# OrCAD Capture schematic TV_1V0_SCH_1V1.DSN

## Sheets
1 Cover: title: 01-Cover; rev: 1.1; company: Shenzhen Test Technology Co., Ltd.; note: TV_V1.0
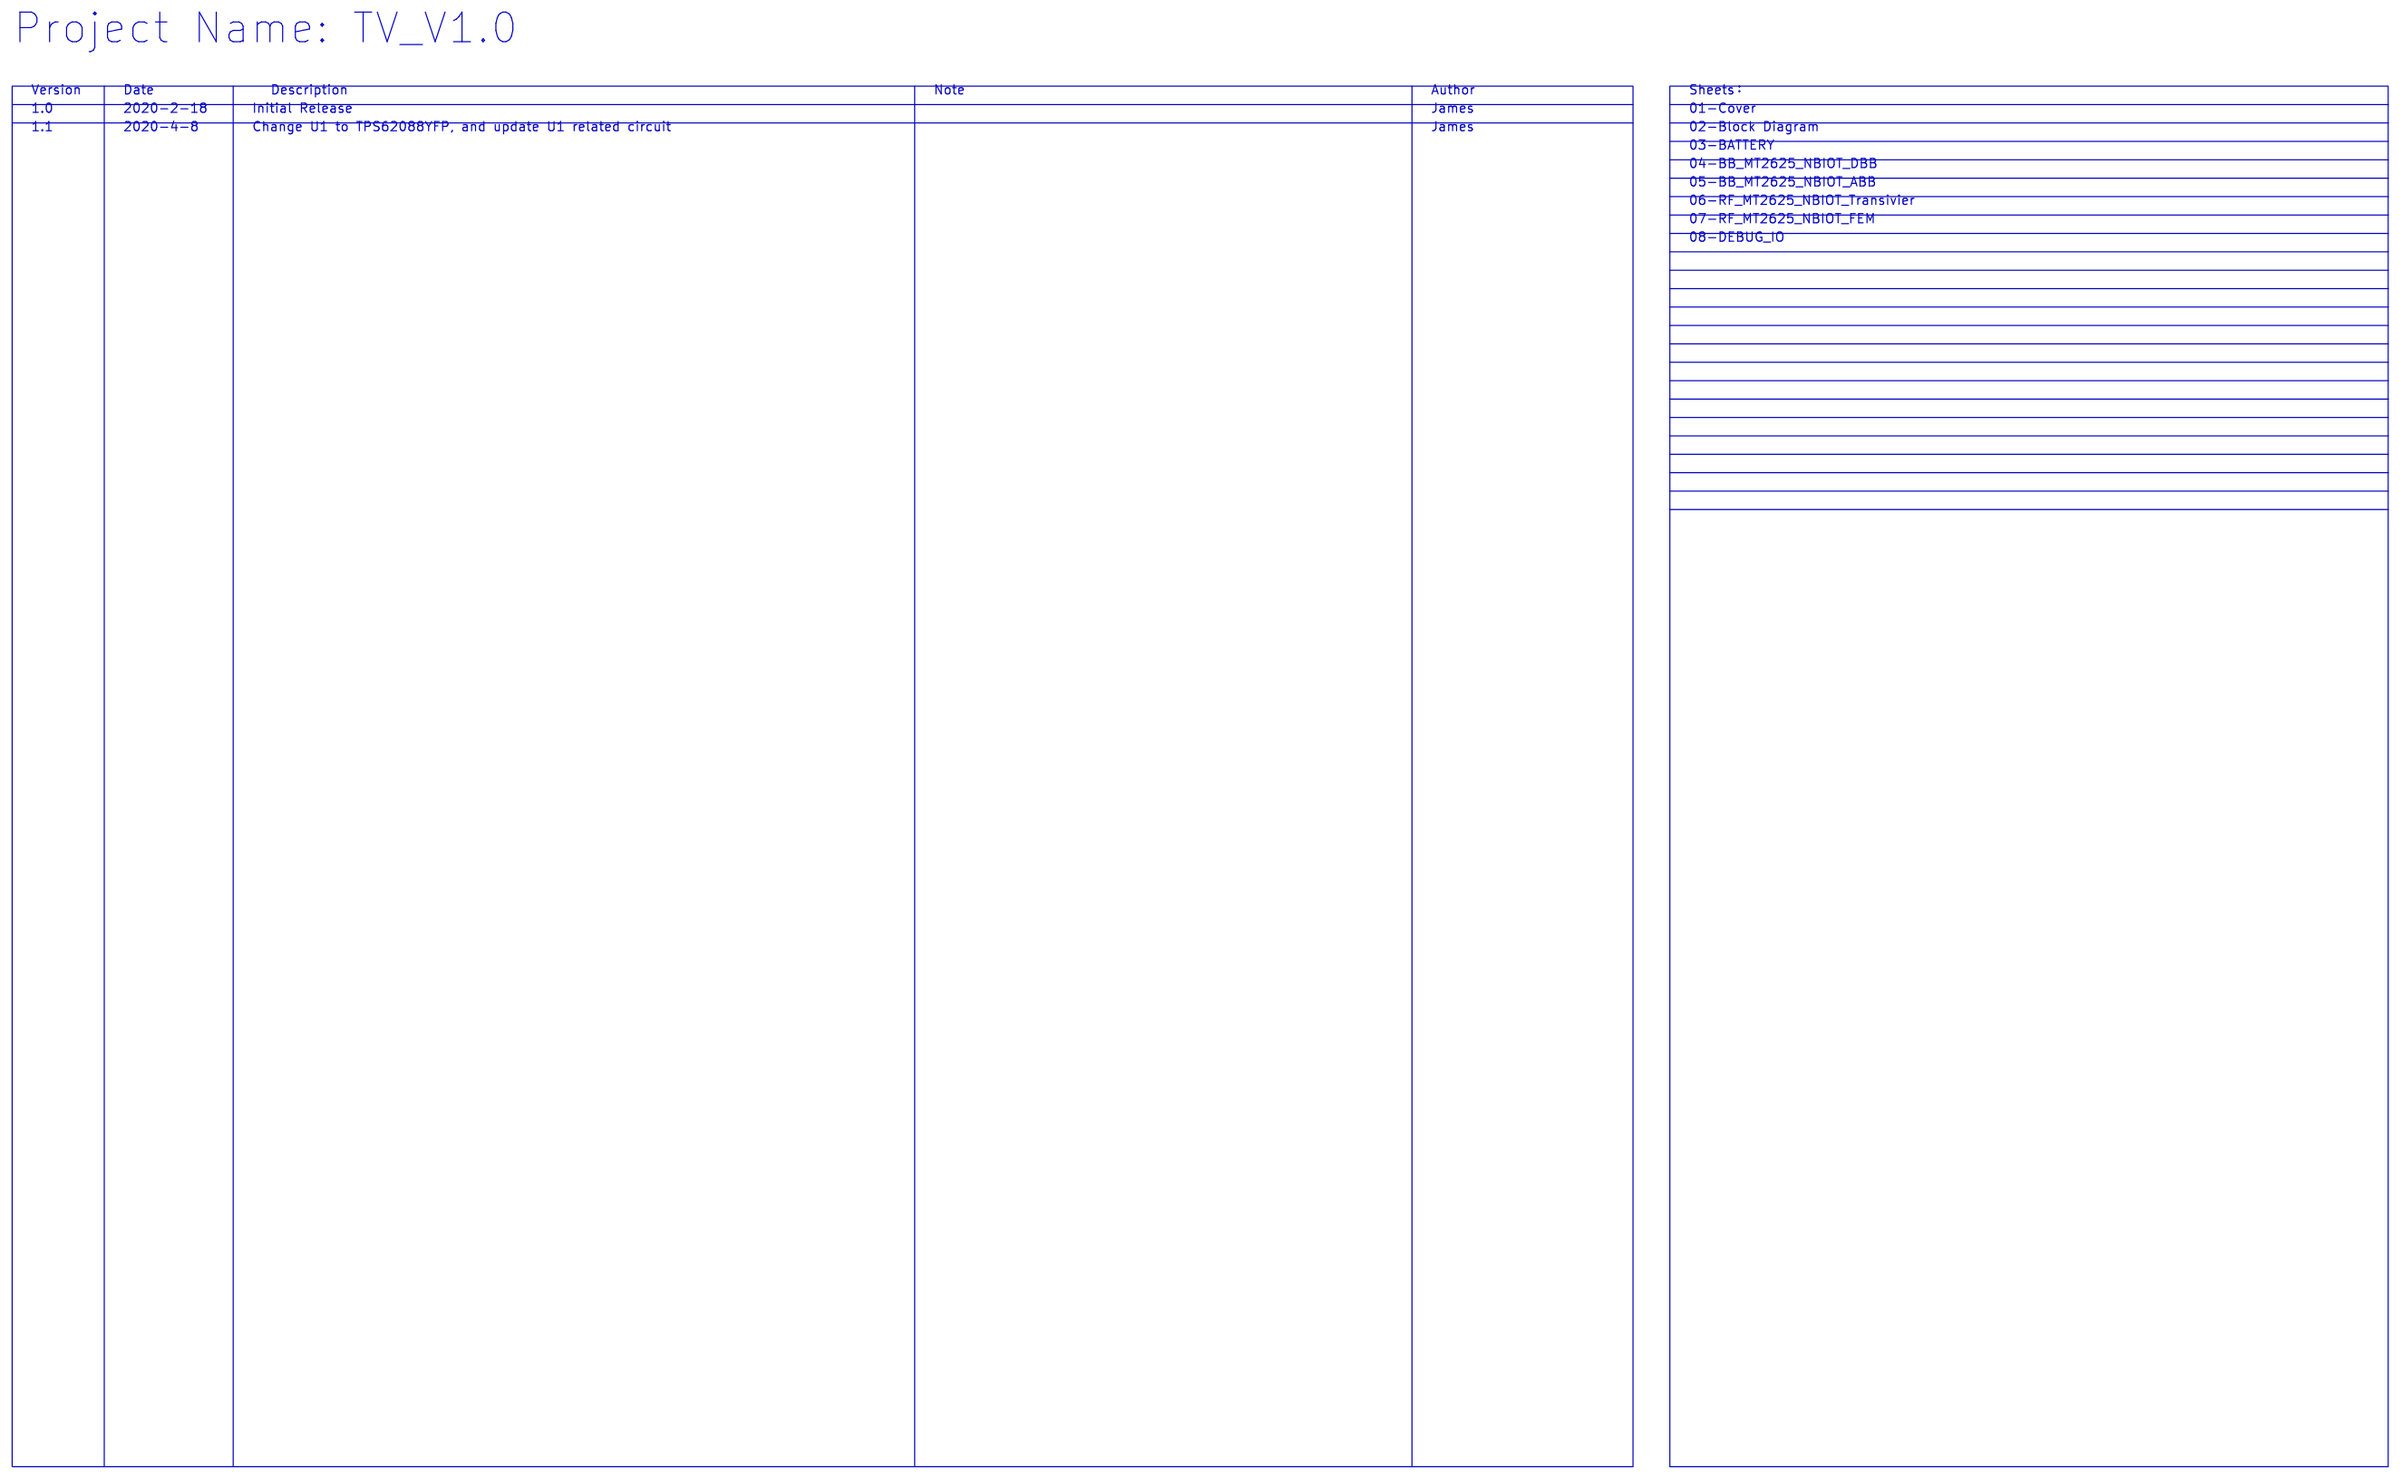
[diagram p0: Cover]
2 Block Diagram: title: 02-Block Diagram
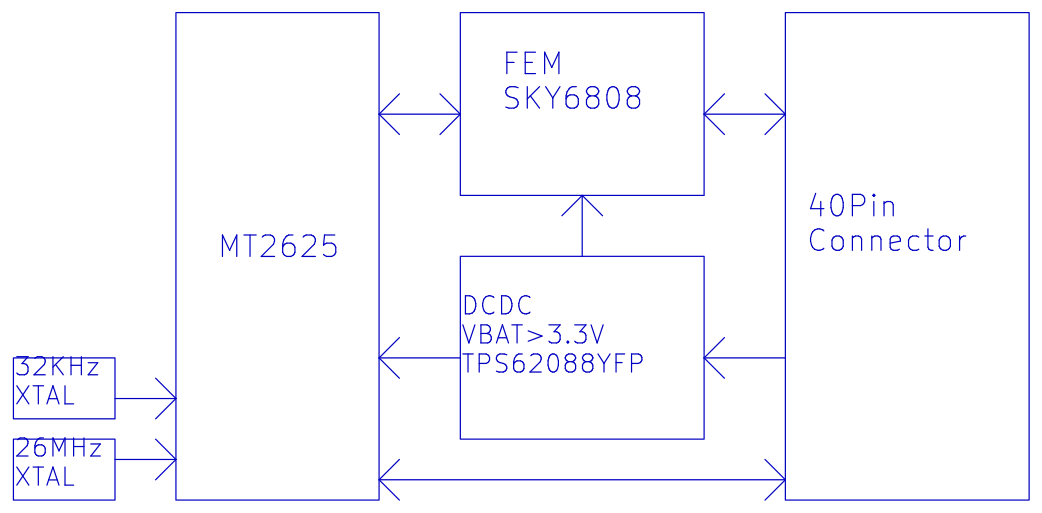
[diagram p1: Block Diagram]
3 BATTERY: size B; title: 03-BATTERY
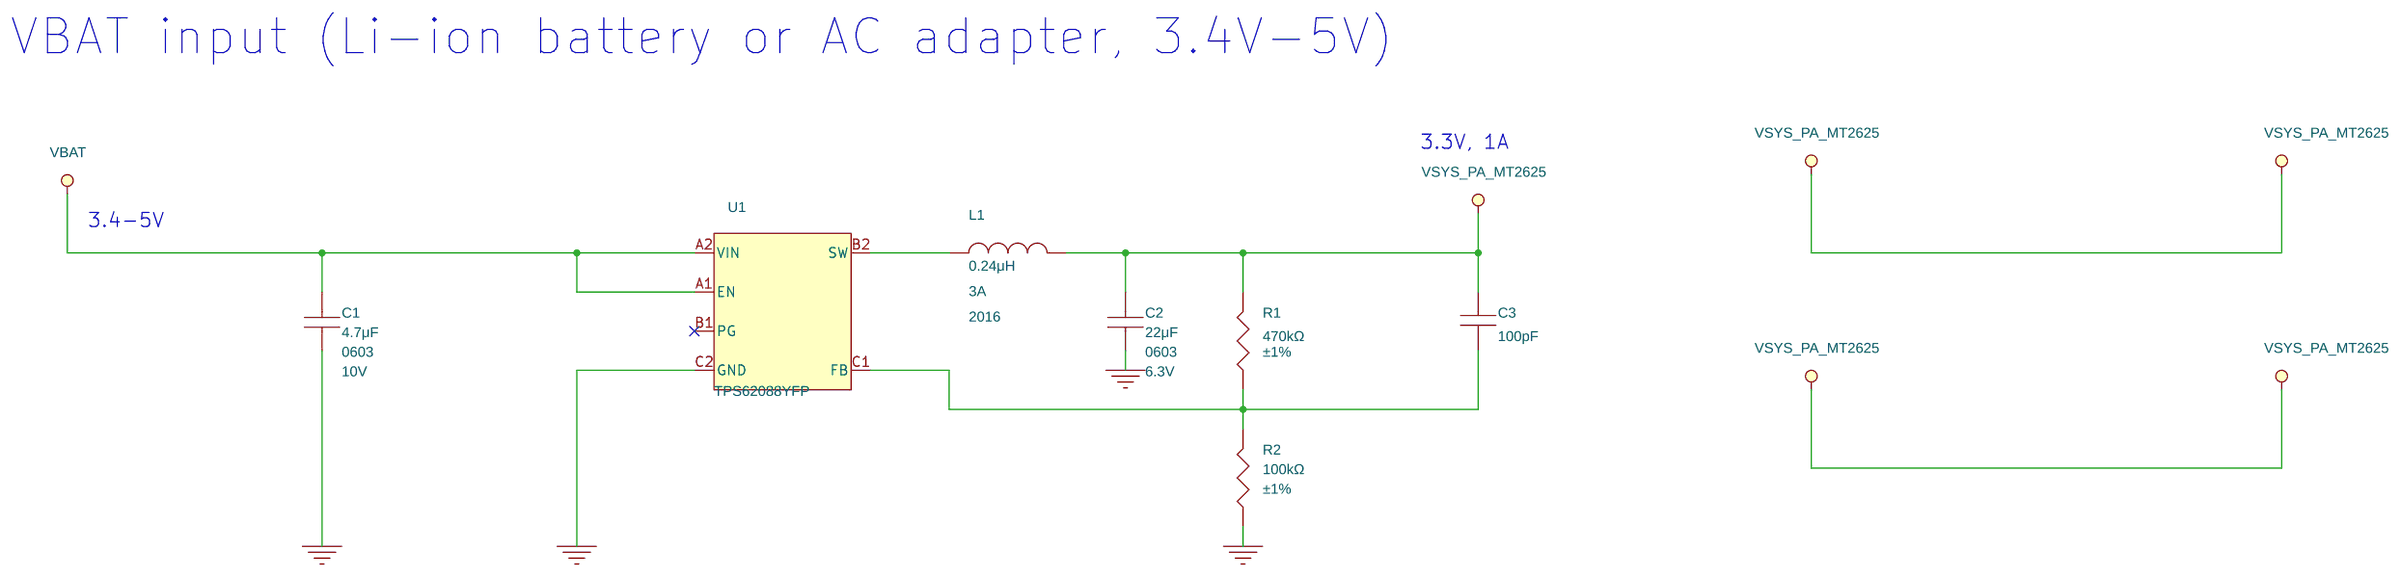
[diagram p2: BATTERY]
4 BB_MT2625_NBIOT_DBB: size B; title: 04-BB_MT2625_NBIOT_DBB
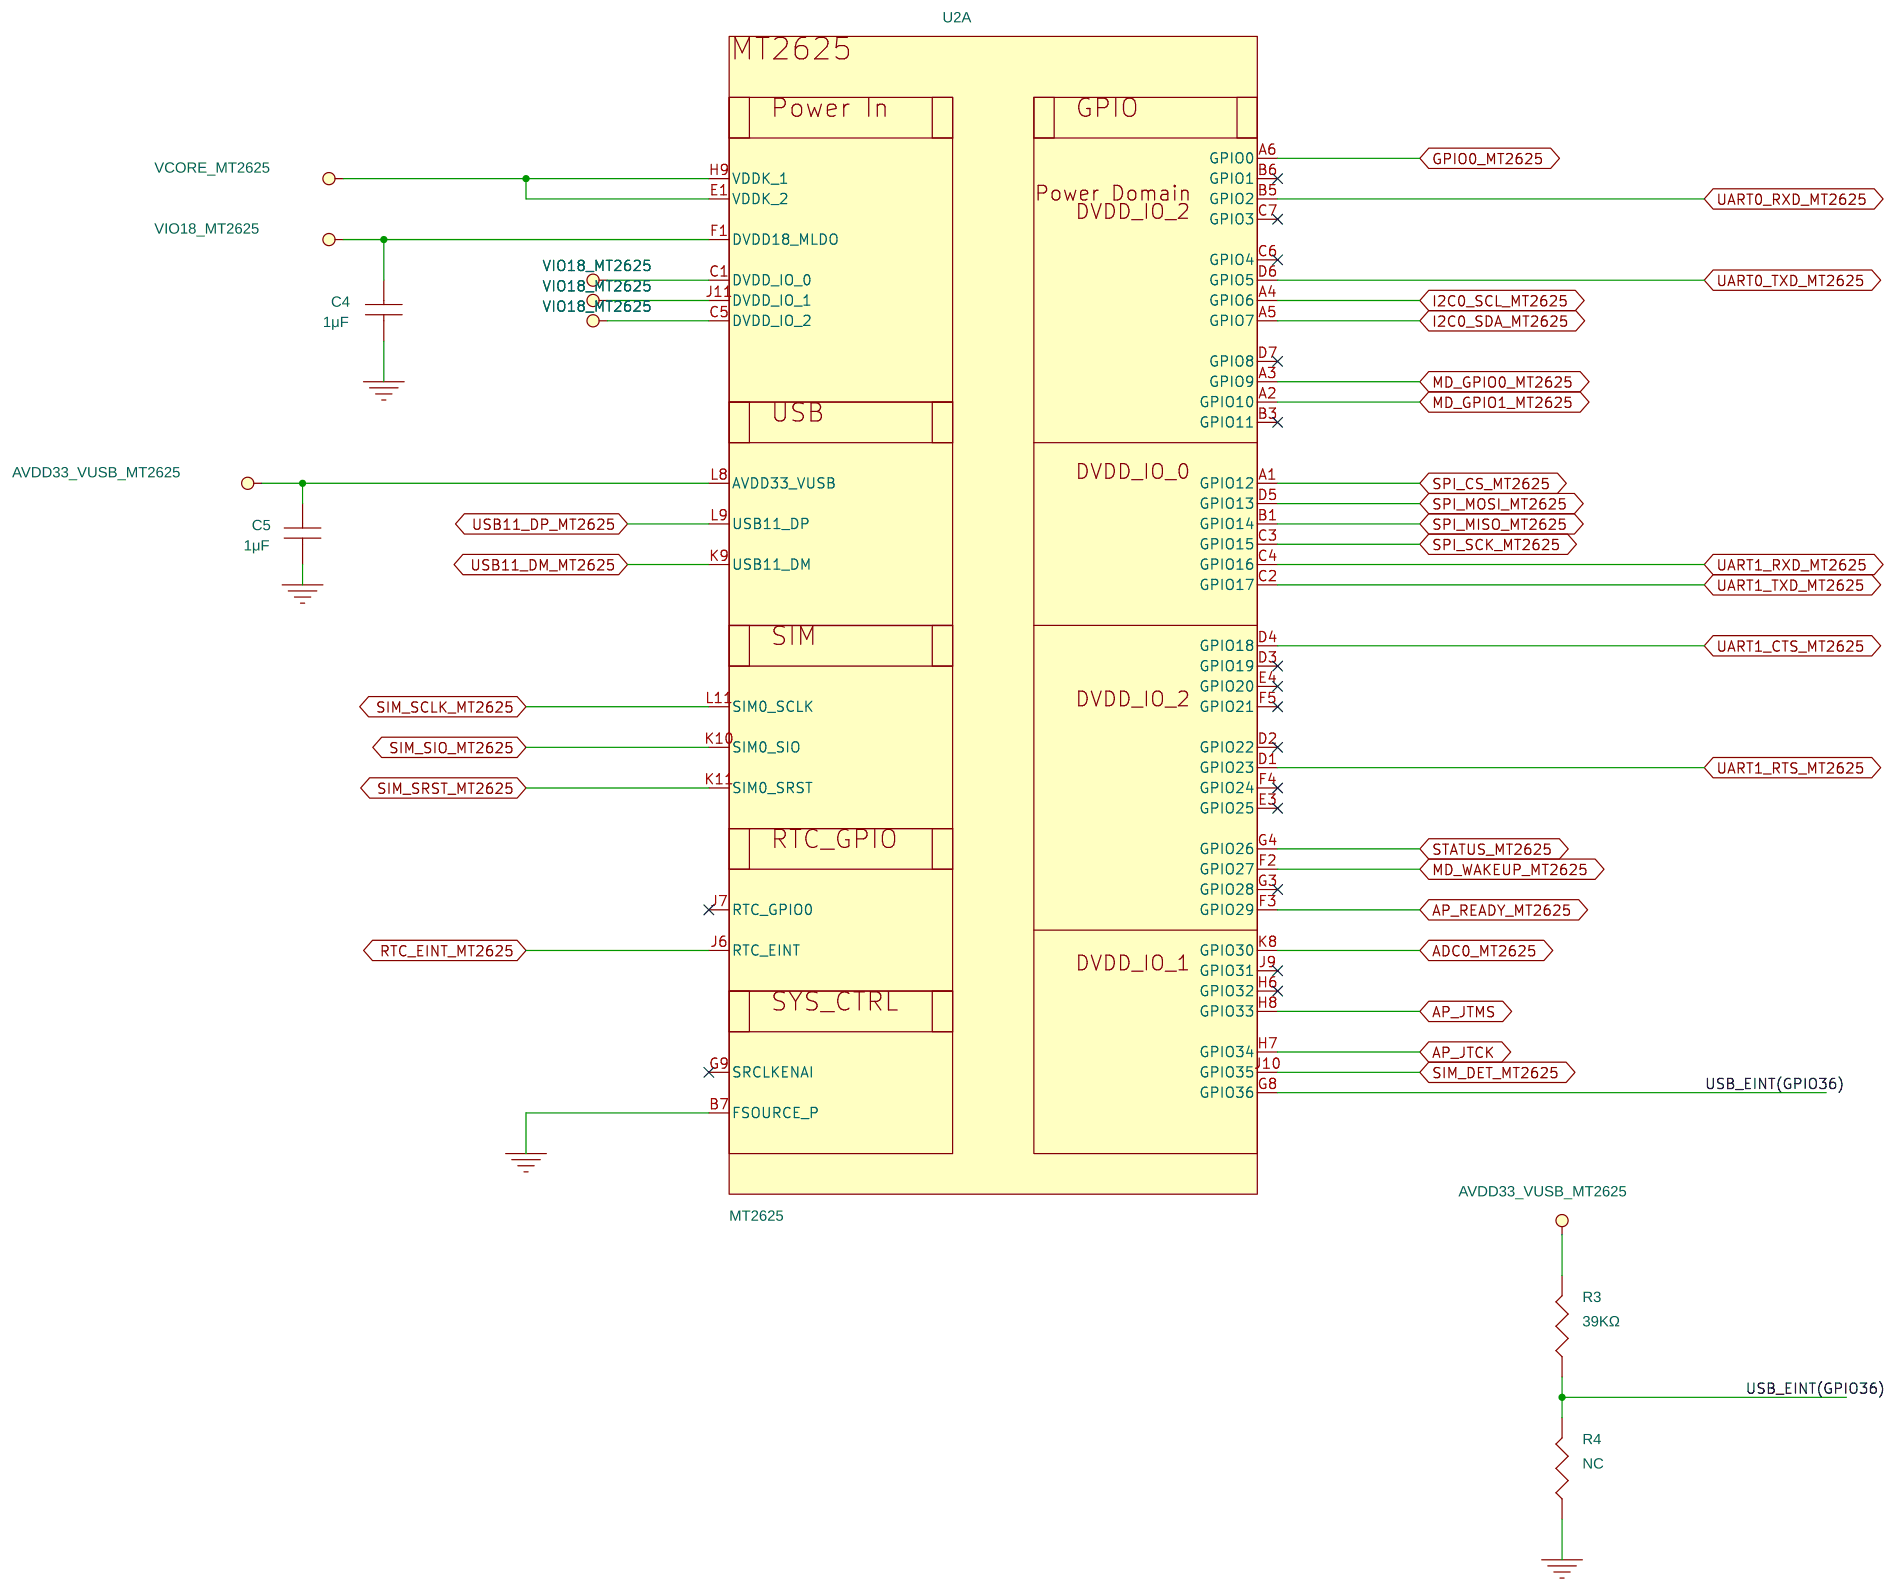
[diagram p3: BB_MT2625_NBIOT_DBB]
5 BB_MT2625_NBIOT_ABB: size B; title: 05-BB_MT2625_NBIOT_ABB
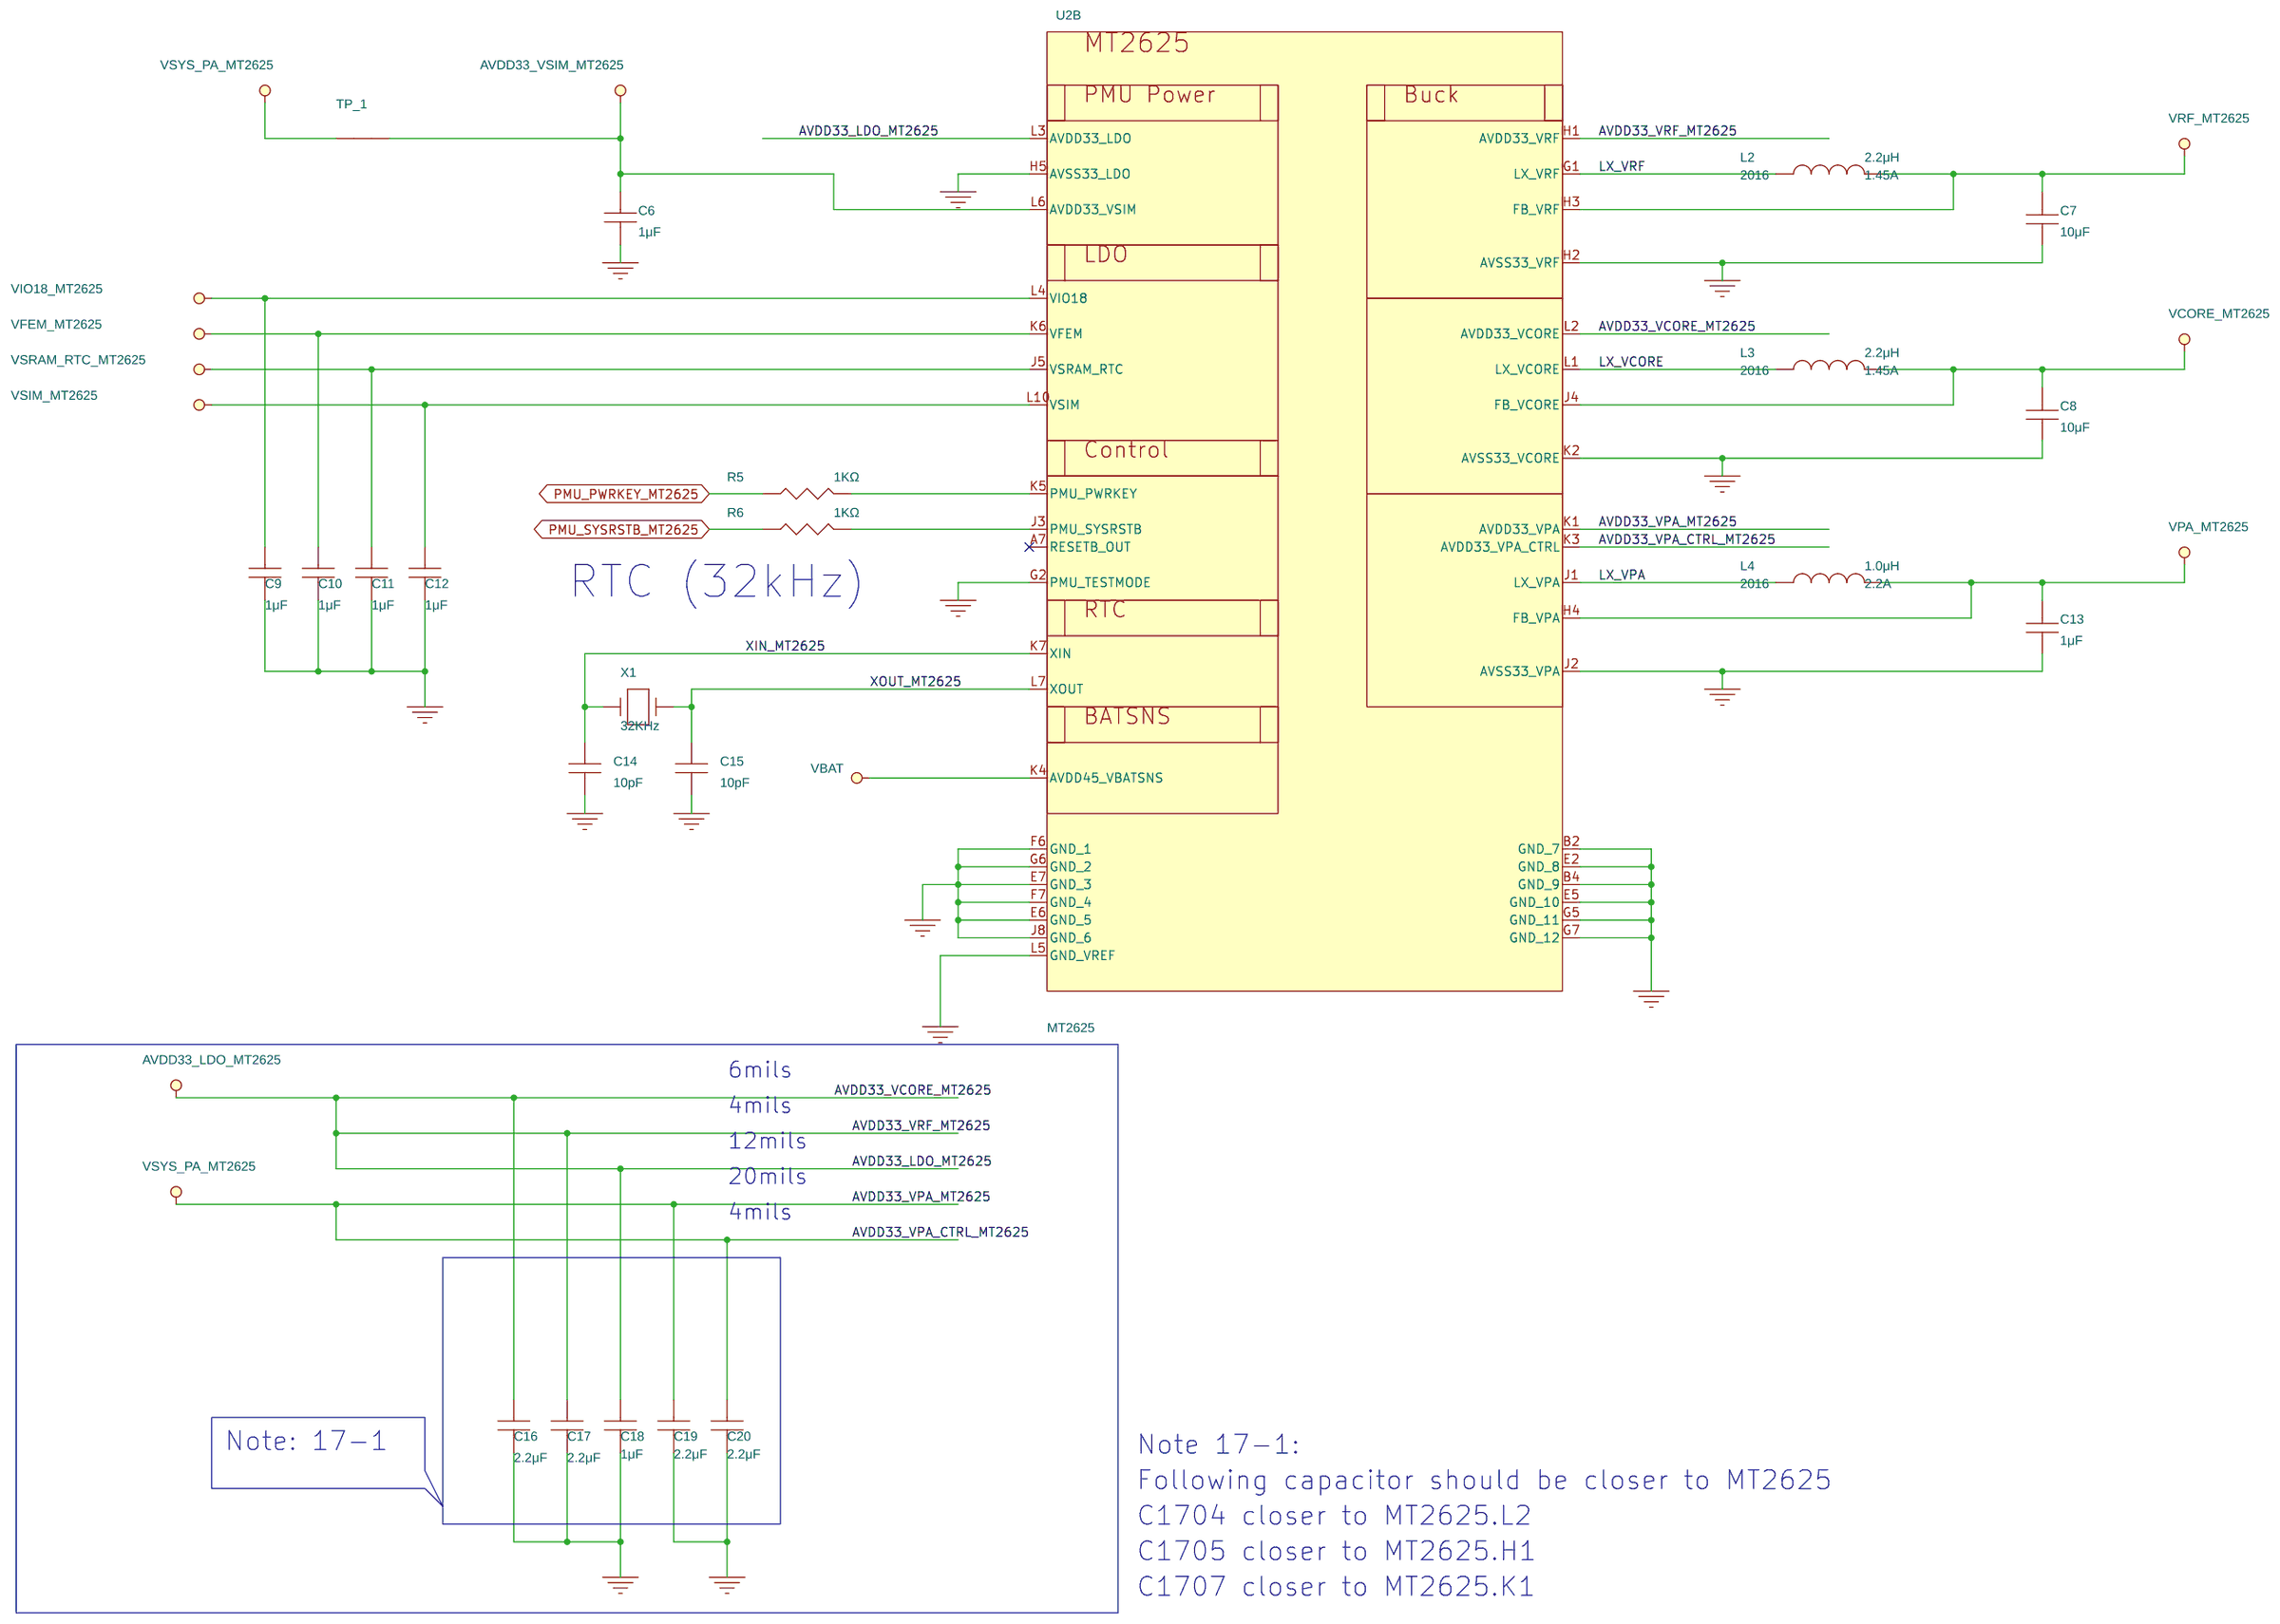
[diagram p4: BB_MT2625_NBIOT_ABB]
6 RF_MT2625_NBIOT_Transivier: size B; title: 06-RF_MT2625_NBIOT_Transivier
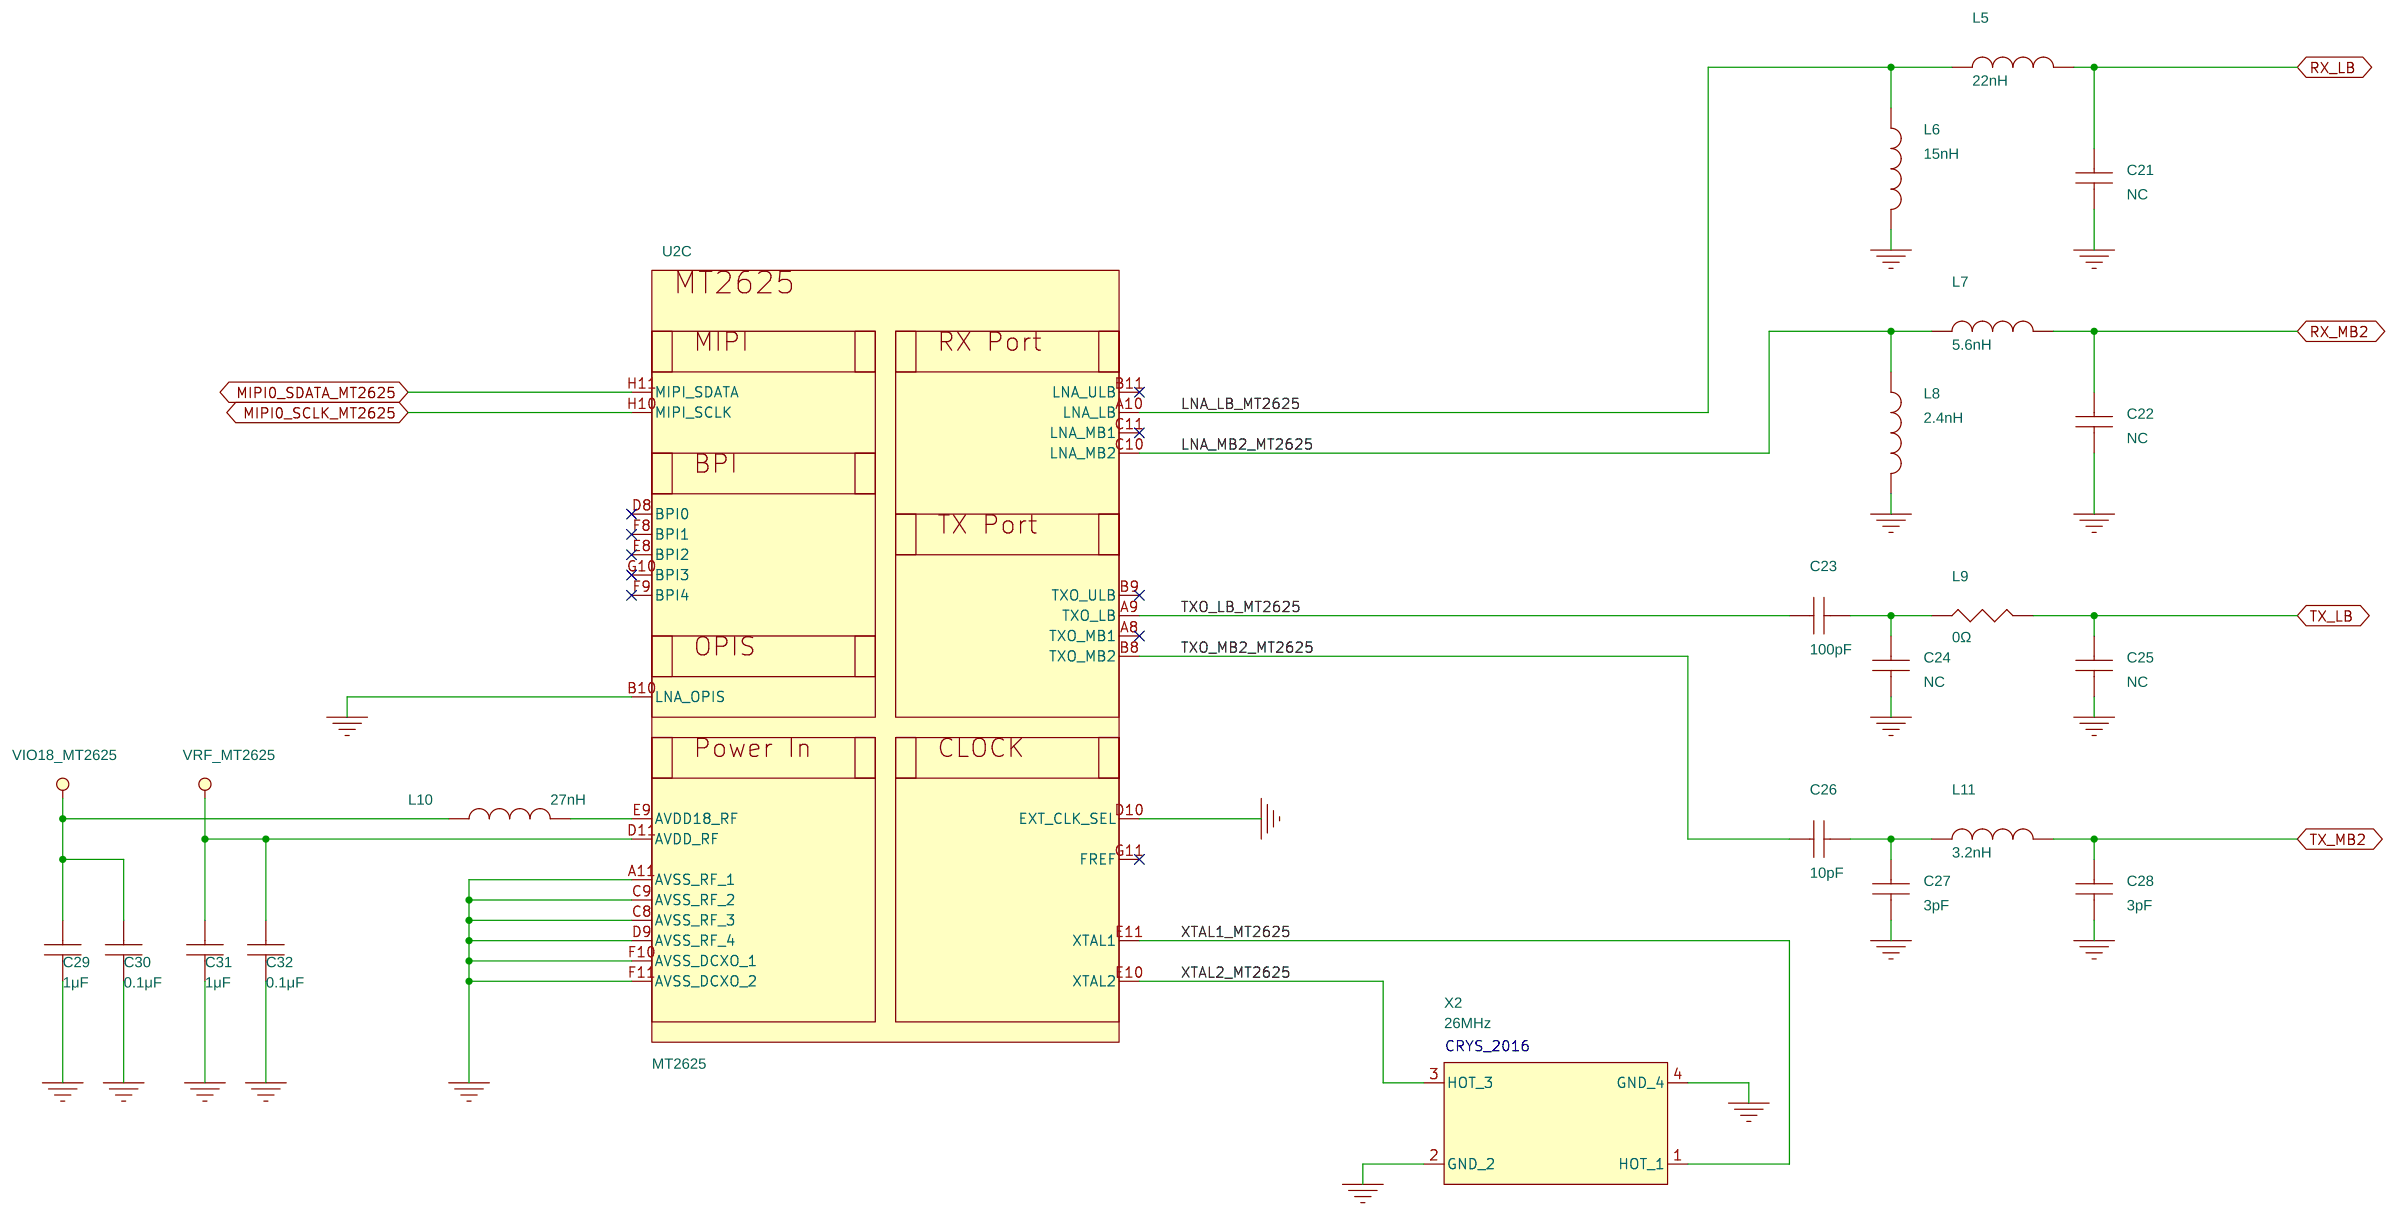
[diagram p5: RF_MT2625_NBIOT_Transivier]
7 RF_MT2625_NBIOT_FEM: size B; title: 07-RF_MT2625_NBIOT_FEM
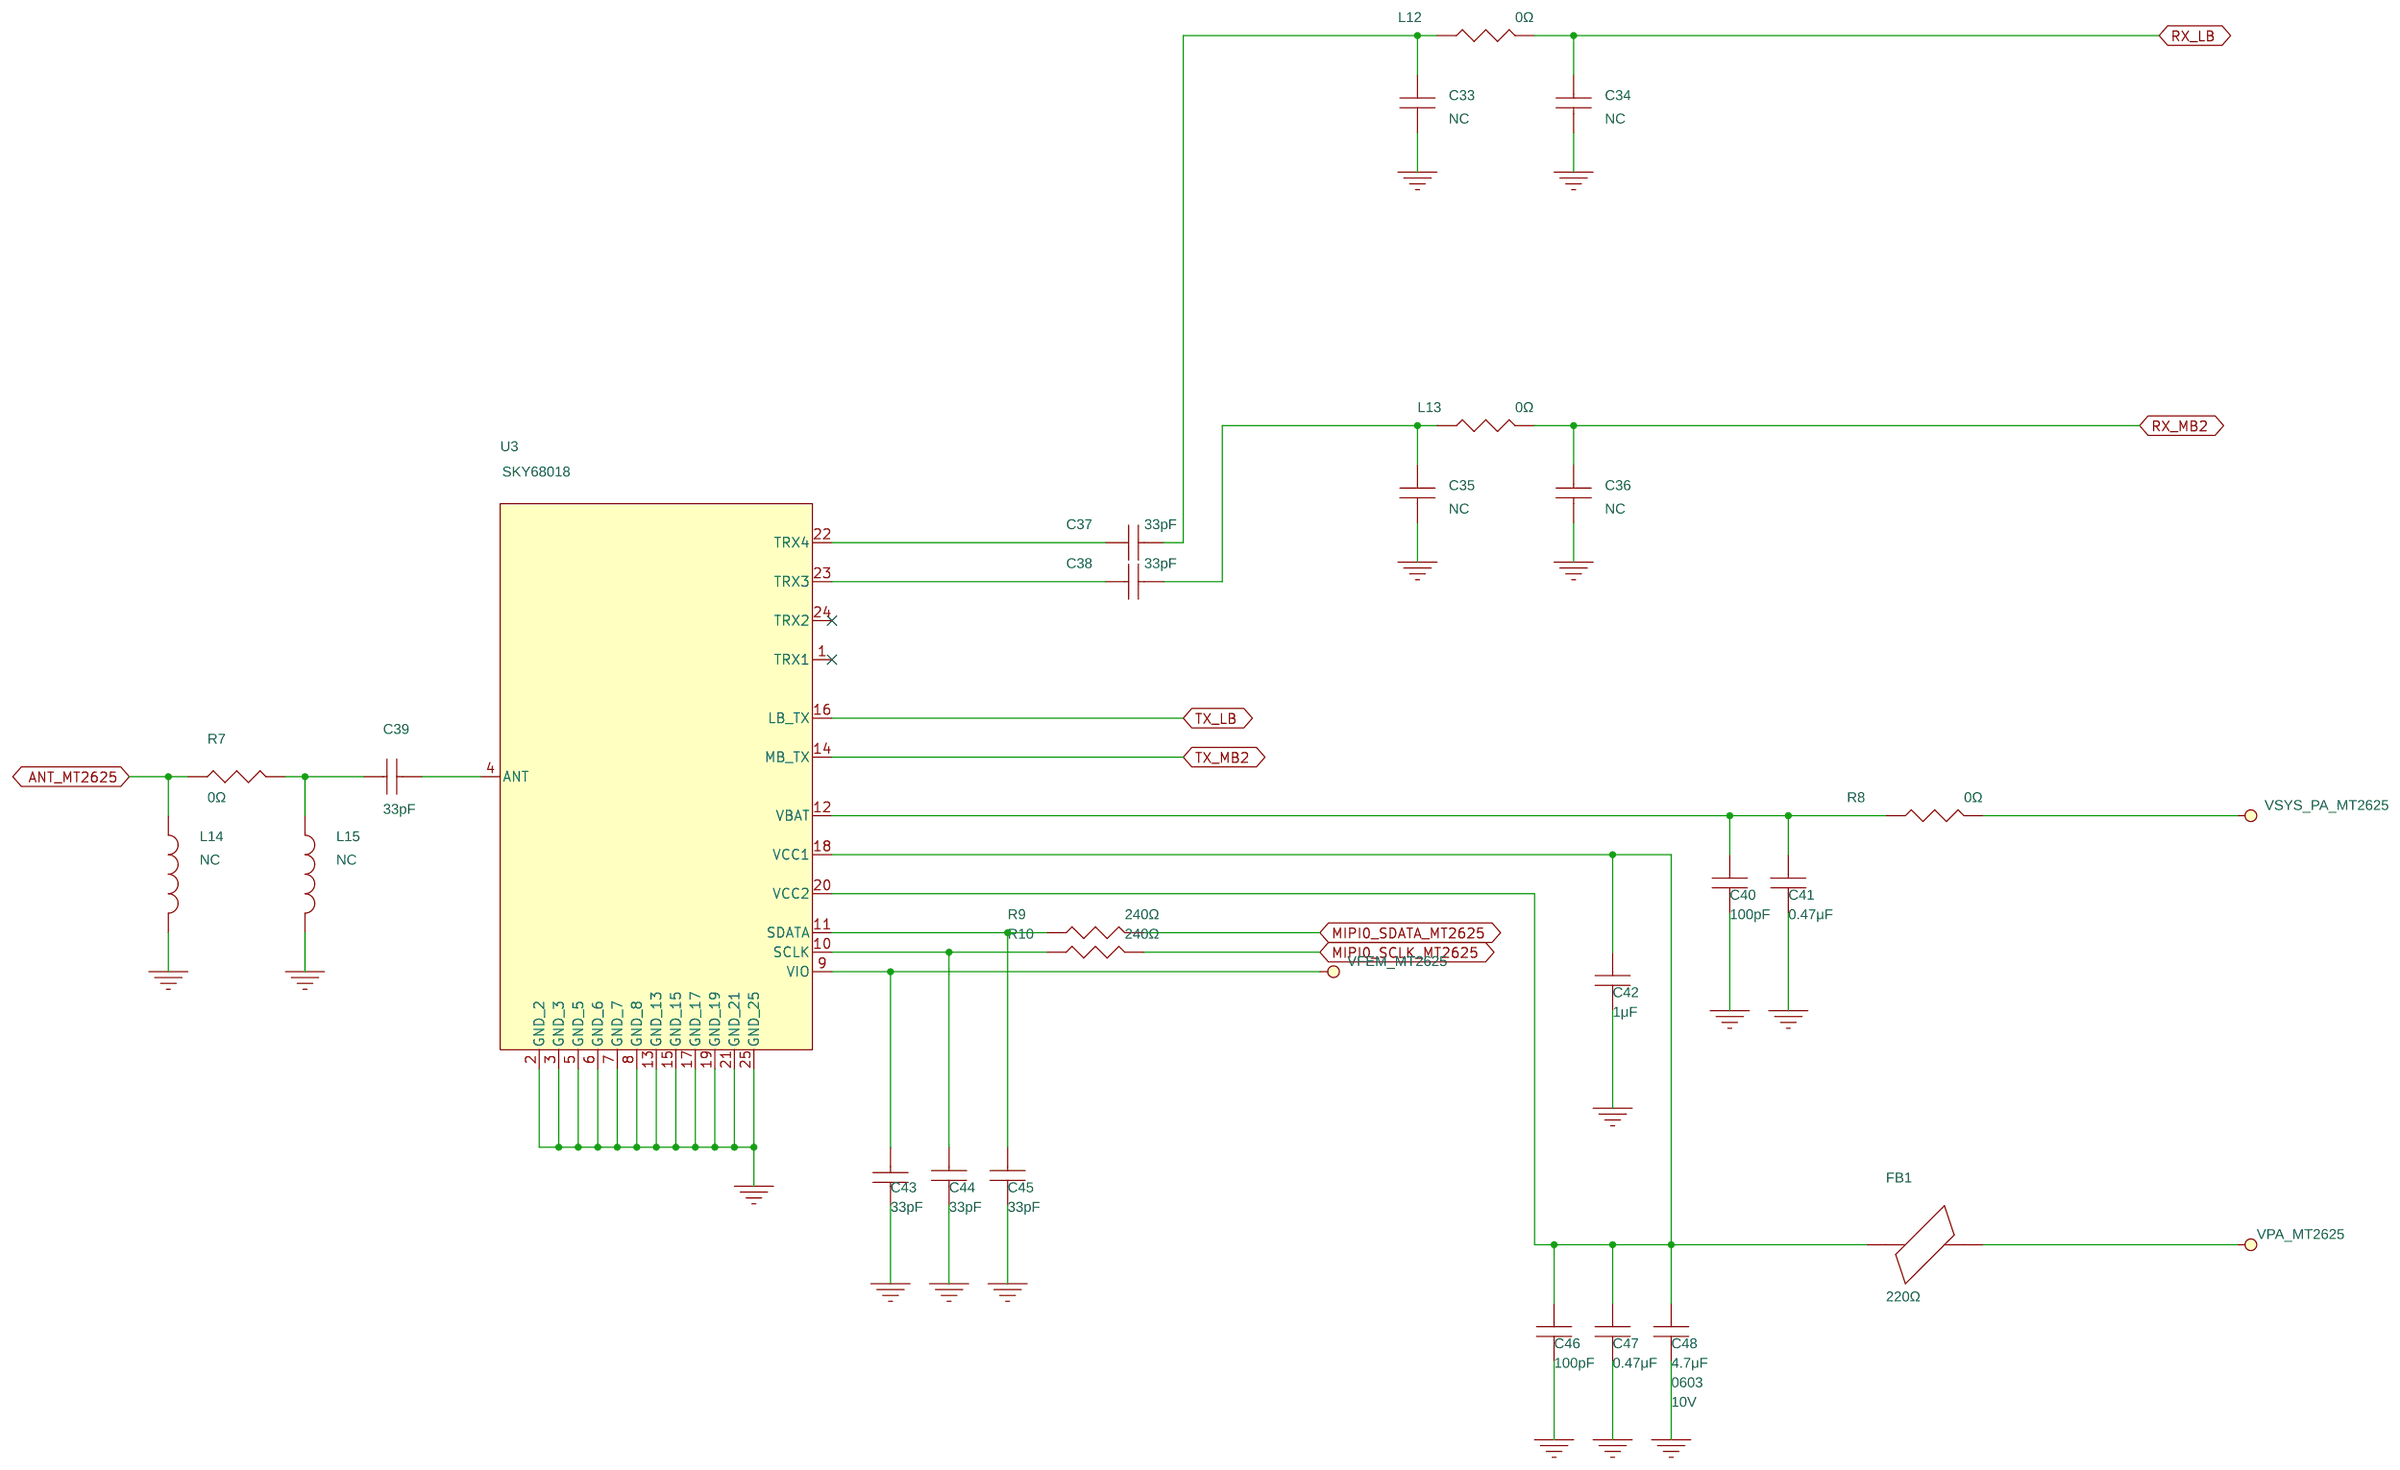
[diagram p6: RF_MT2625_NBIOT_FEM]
8 DEBUG_IO: size B; title: 08-DEBUG_IO
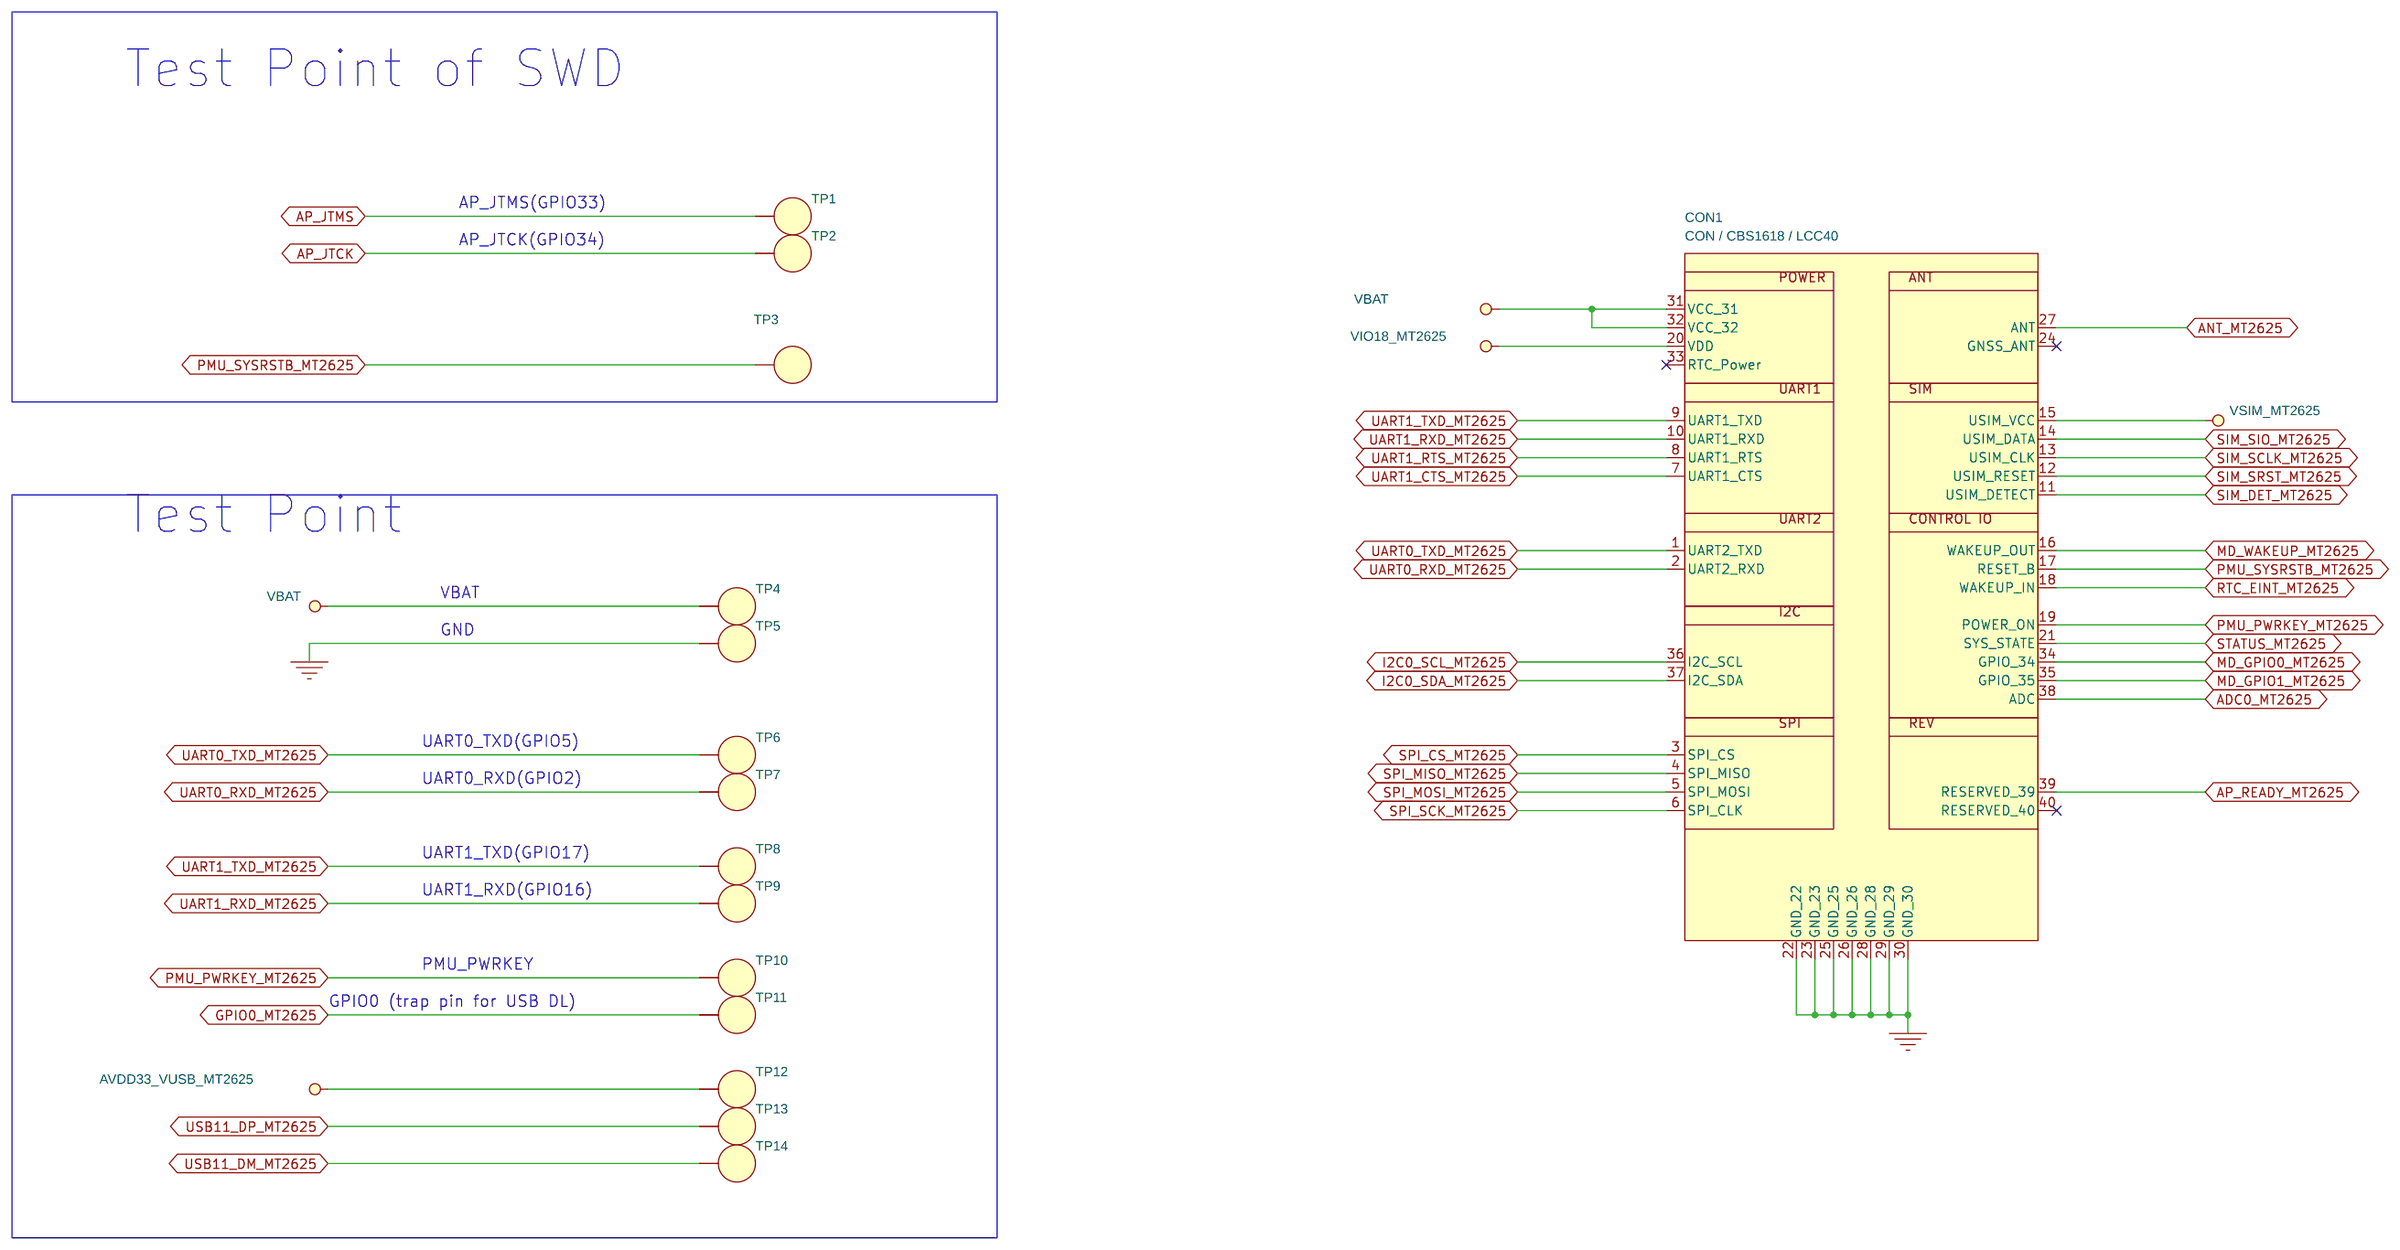
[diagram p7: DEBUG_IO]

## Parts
sheet BATTERY
C1  4.7μF  [C0603N]
C2  22μF  [C0603N]
C3  100pF  [C0201N]
L1  0.24μH  [L2016N]
R1  470kΩ  [R0201N]
R2  100kΩ  [R0201N]
U1  TPS62088YFP  [TPS62088YFP]
sheet BB_MT2625_NBIOT_ABB
C6  1μF  [C0201N]
C7  10μF  [C0402N]
C8  10μF  [C0402N]
C9  1μF  [C0201N]
C10  1μF  [C0201N]
C11  1μF  [C0201N]
C12  1μF  [C0201N]
C13  1μF  [C0402N]
C14  10pF  [C0201N]
C15  10pF  [C0201N]
C16  2.2μF  [C0201N]
C17  2.2μF  [C0201N]
C18  1μF  [C0201N]
C19  2.2μF  [C0402N]
C20  2.2μF  [C0201N]
L2  2.2μH  [L2016N]
L3  2.2μH  [L2016N]
L4  1.0μH  [L2016N]
R5  1KΩ  [R0201N]
R6  1KΩ  [R0201N]
TP_1  SHORT  [NC-4MIL]
X1  32KHz  [CM8V-T1A]
sheet BB_MT2625_NBIOT_DBB
C4  1μF  [C0201N]
C5  1μF  [C0201N]
R3  39KΩ  [R0201N]
R4  NC  [R0402N]
sheet DEBUG_IO
CON1  CON / CBS1618 / LCC40  [CBS1618]
TP1  TEST_POINT  [TP_D2mm]
TP2  TEST_POINT  [TP_D2mm]
TP3  TEST_POINT  [TP_D2mm]
TP4  TEST_POINT  [TP_D2mm]
TP5  TEST_POINT  [TP_D2mm]
TP6  TEST_POINT  [TP_D2mm]
TP7  TEST_POINT  [TP_D2mm]
TP8  TEST_POINT  [TP_D2mm]
TP9  TEST_POINT  [TP_D2mm]
TP10  TEST_POINT  [TP_D2mm]
TP11  TEST_POINT  [TP_D2mm]
TP12  TEST_POINT  [TP_D2mm]
TP13  TEST_POINT  [TP_D2mm]
TP14  TEST_POINT  [TP_D2mm]
sheet RF_MT2625_NBIOT_FEM
C33  NC  [C0201N]
C34  NC  [C0201N]
C35  NC  [C0201N]
C36  NC  [C0201N]
C37  33pF  [C0201N]
C38  33pF  [C0201N]
C39  33pF  [C0201N]
C40  100pF  [C0201N]
C41  0.47μF  [C0201N]
C42  1μF  [C0201N]
C43  33pF  [C0201N]
C44  33pF  [C0201N]
C45  33pF  [C0201N]
C46  100pF  [C0201N]
C47  0.47μF  [C0201N]
C48  4.7μF  [C0603N]
FB1  220Ω  [L0402N]
L12  0Ω  [R0201N]
L13  0Ω  [R0201N]
L14  NC  [L0201N]
L15  NC  [L0201N]
R7  0Ω  [R0201N]
R8  0Ω  [R0201N]
R9  240Ω  [R0201N]
R10  240Ω  [R0201N]
U3  SKY68018  [SKY68000-11]
sheet RF_MT2625_NBIOT_Transivier
C21  NC  [C0201N]
C22  NC  [C0201N]
C23  100pF  [C0201N]
C24  NC  [C0201N]
C25  NC  [C0201N]
C26  10pF  [C0201N]
C27  3pF  [C0201N]
C28  3pF  [C0201N]
C29  1μF  [C0201N]
C30  0.1μF  [C0201N]
C31  1μF  [C0201N]
C32  0.1μF  [C0201N]
L5  22nH  [L0201N]
L6  15nH  [L0201N]
L7  5.6nH  [L0201N]
L8  2.4nH  [L0201N]
L9  0Ω  [R0201N]
L10  27nH  [L0201N]
L11  3.2nH  [L0201N]
U2  MT2625  [MT2625]  (sections A,B,C)
X2  26MHz  [FW260WFMT1]

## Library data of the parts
C1 C48 = C0603: CAP|MLCC|0603|4.7μF±10%|10V|X5R; Height (Max): 0.90mm; Manufacturer: muRata; Manufacturer Part Number: GRM188R61A475KE15D; Package / Case: 0603; ROHS: Yes; SMT: Yes; Size / Dimension: 1.60mm x 0.80mm; Tolerance: ±10%; Unit: PCS; Voltage - Rated: 10V
C2 = C0603: CAP|MLCC|0603|22μF±20%|6.3V|X5R; Height (Max): 1.00mm; Manufacturer: muRata; Manufacturer Part Number: GRM188R60J226MEA0D; Package / Case: 0603; ROHS: Yes; SMT: Yes; Size / Dimension: 1.60mm x 0.80mm; Tolerance: ±20%; Unit: PCS; Voltage - Rated: 6.3V
C3 C23 C40 C46 = C0201: CAP|MLCC|0201|100pF±5%|25V|C0G; Height (Max): 0.33mm; Manufacturer: muRata; Manufacturer Part Number: GRM0335C1E101JA01D; Package / Case: 0201; Part Number: 351000000039; ROHS: Yes; SMT: Yes; Size / Dimension: 0.60mm x 0.30mm; Tolerance: ±5%; Unit: PCS; Voltage - Rated: 25V
L1 = L2016: IND|Wire Wound|2016|0.24μH±20%|3A|40mΩ|Q-|145MHz|Closed magnetic; Current Rating (Amps): 3A; Height (Max): 1.0mm; Manufacturer: Sunlord; Manufacturer Part Number: WPN201610HR24MT; Package / Case: 2016; ROHS: Yes; SMT: Yes; Size / Dimension: 2.0mm x 1.6mm; Unit: PCS
R1 = R0201_1%: RES|Thick Film|0201|470kΩ±1%|1/20W|±200ppm/°C; Height (Max): 0.26mm; Manufacturer: Yageo; Manufacturer Part Number: RC0201FR-07470KL; Package / Case: 0201; Power (Watts): 1/20W; ROHS: Yes; SMT: Yes; Size / Dimension: 0.60mm x 0.30mm; Tolerance: ±1%; Unit: PCS
R2 = R0201_1%: RES|Thick Film|0201|100kΩ±1%|1/20W|±200ppm/°C; Height (Max): 0.26mm; Manufacturer: Yageo; Manufacturer Part Number: RC0201FR-07100KL; Package / Case: 0201; Part Number: 301000000147; Power (Watts): 1/20W; ROHS: Yes; SMT: Yes; Size / Dimension: 0.60mm x 0.30mm; Tolerance: ±1%; Unit: PCS
U1 = TPS62088_1
C4-C6 C9-C12 C18 C29 C31 C42 = C0201: CAP|MLCC|0201|1μF±20%|6.3V|X5R; Height (Max): 0.33mm; Manufacturer: muRata; Manufacturer Part Number: GRM033R60J105MEA2D; Package / Case: 0201; Part Number: 351000000066; ROHS: Yes; SMT: Yes; Size / Dimension: 0.60mm x 0.30mm; Tolerance: ±20%; Unit: PCS; Voltage - Rated: 6.3V
C7 C8 = C0402: CAP|MLCC|0402|10μF±20%|6.3V|X5R; Height (Max): 0.65mm; Manufacturer: muRata; Manufacturer Part Number: GRM155R60J106ME15D; Package / Case: 0402; ROHS: Yes; SMT: Yes; Size / Dimension: 1.00mm x 0.50mm; Tolerance: ±20%; Unit: PCS; Voltage - Rated: 6.3V
C13 = C0402: CAP|MLCC|0402|1μF±10%|6.3V|X5R; Height (Max): 0.33mm; Manufacturer: muRata; Manufacturer Part Number: GRM155R60J105KE19D; Package / Case: 0402; Part Number: 352000000059; ROHS: Yes; SMT: Yes; Size / Dimension: 1.00mm x 0.50mm; Tolerance: ±10%; Unit: PCS; Voltage - Rated: 6.3V
C14 C15 C26 = C0201: CAP|MLCC|0201|10pF±5%|25V|C0G; Height (Max): 0.33mm; Manufacturer: muRata; Manufacturer Part Number: GRM0335C1E100JA01D; Package / Case: 0201; Part Number: 351000000024; ROHS: Yes; SMT: Yes; Size / Dimension: 0.60mm x 0.30mm; Tolerance: ±5%; Unit: PCS; Voltage - Rated: 25V
C16 C17 C20 = C0201: CAP|MLCC|0201|2.2μF±20%|6.3V|X5R; Height (Max): 0.39mm; Manufacturer: muRata; Manufacturer Part Number: GRM033R60J225ME47D; Package / Case: 0201; Part Number: 351000000129; ROHS: Yes; SMT: Yes; Size / Dimension: 0.60mm x 0.30mm; Tolerance: ±20%; Unit: PCS; Voltage - Rated: 6.3V
C19 = C0402: CAP|MLCC|0402|2.2μF±10%|6.3V|X5R; Height (Max): 0.55mm; Manufacturer: muRata; Manufacturer Part Number: GRM155R60J225KE95D; Package / Case: 0402; ROHS: Yes; SMT: Yes; Size / Dimension: 1.00mm x 0.50mm; Tolerance: ±10%; Unit: PCS; Voltage - Rated: 6.3V
L2 L3 = L2016: IND|Wire Wound|2016|2.2μH±20%|1.45A|170mΩ|Q-|39MHz|Closed magnetic; Current Rating (Amps): 1.45A; Height (Max): 1.0mm; Manufacturer: Sunlord; Manufacturer Part Number: WPN201610H2R2MT; Package / Case: 2016; ROHS: Yes; SMT: Yes; Size / Dimension: 2.0mm x 1.6mm; Unit: PCS
L4 = L2016: IND|Wire Wound|2016|1.0μH±20%|2.2A|70mΩ|Q-|65MHz|Closed magnetic; Current Rating (Amps): 2.2A; Height (Max): 1.0mm; Manufacturer: Sunlord; Manufacturer Part Number: WPN201610H1R0MTY01; Package / Case: 2016; ROHS: Yes; SMT: Yes; Size / Dimension: 2.0mm x 1.6mm; Unit: PCS
R5 R6 = R0201: RES|Thick Film|0201|1KΩ±5%|1/20W|±200ppm/°C; Height (Max): 0.26mm; Manufacturer: Yageo; Manufacturer Part Number: RC0201JR-071KL; Package / Case: 0201; Part Number: 301000000034; Power (Watts): 1/20W; ROHS: Yes; SMT: Yes; Size / Dimension: 0.60mm x 0.30mm; Tolerance: ±5%; Unit: PCS
TP_1 = NO_PAD_0402_SMD_1: SH1001; ebom: TBD
X1 = X_32_0.768K: XTAL|32KHz|7pF; Manufacturer Part Number: SC-20S; ROHS: Yes; SMT: Yes; Unit: PCS
R3 = R0201: RES|Thick Film|0201|39KΩ±5%|1/20W|±200ppm/°C; Height (Max): 0.26mm; Manufacturer: Yageo; Manufacturer Part Number: RC0201JR-0739KL; Package / Case: 0201; Power (Watts): 1/20W; ROHS: Yes; SMT: Yes; Size / Dimension: 0.60mm x 0.30mm; Tolerance: ±5%; Unit: PCS
R4 = R0402: RES|Thick Film|0402|1KΩ±5%|1/16W|±100ppm/°C; BOM_IGNORE: TRUE; Height (Max): 0.40mm; Manufacturer: Yageo; Manufacturer Part Number: RC0402JR-071KL; Package / Case: 0402; Part Number: 302000000041; Power (Watts): 1/16W; ROHS: Yes; SMT: Yes; Size / Dimension: 1.00mm x 0.50mm; Tolerance: ±5%; Unit: PCS
CON1 = CBS1618_LCC40_1
TP1-TP14 = TEST_POINT: TP|Circle|SMD|D2mm; Size / Dimension: D2mm
C21 C22 C24 C25 C33-C36 = C0201: CAP|MLCC|0201|12pF±5%|25V|C0G; BOM_IGNORE: TRUE; Height (Max): 0.33mm; Manufacturer: muRata; Manufacturer Part Number: GRM0335C1E120JA01D; Package / Case: 0201; Part Number: 351000000027; ROHS: Yes; SMT: Yes; Size / Dimension: 0.60mm x 0.30mm; Tolerance: ±5%; Unit: PCS; Voltage - Rated: 25V
C37-C39 C43-C45 = C0201: CAP|MLCC|0201|33pF±5%|25V|C0G; Height (Max): 0.33mm; Manufacturer: muRata; Manufacturer Part Number: GRM0335C1E330JA01D; Package / Case: 0201; Part Number: 351000000031; ROHS: Yes; SMT: Yes; Size / Dimension: 0.60mm x 0.30mm; Tolerance: ±5%; Unit: PCS; Voltage - Rated: 25V
C41 C47 = C0201: CAP|MLCC|0201|0.47μF±10%|6.3V|X5R; Height (Max): 0.33mm; Manufacturer: muRata; Manufacturer Part Number: GRM033R60J474KE90D; Package / Case: 0201; Part Number: 351000000131; ROHS: Yes; SMT: Yes; Size / Dimension: 0.60mm x 0.30mm; Tolerance: ±10%; Unit: PCS; Voltage - Rated: 6.3V
FB1 = BEAD: Ferrite Bead|General|0402|220Ω|600mA|180mΩ|-55~ 125°C; Height (Max): 0.55mm; Manufacturer: muRata; Manufacturer Part Number: BLM15AX221SN1D; Package / Case: 0402; ROHS: Yes; SMT: Yes; Size / Dimension: 1.00mm x 0.55mm; Unit: PCS
L9 L12 L13 R7 R8 = R0201: RES|Thick Film|0201|0ΩJumper|0.5A; Height (Max): 0.26mm; Manufacturer: Yageo; Manufacturer Part Number: RC0201JR-070RL; Package / Case: 0201; Power (Watts): 1/20W; ROHS: Yes; SMT: Yes; Size / Dimension: 0.60mm x 0.30mm; Tolerance: Jumper; Unit: PCS
L14 L15 = L0201: IND|Thin Film|0201|12nH±5%|250mA|700mΩ|Q12|2.9GHz; BOM_IGNORE: TRUE; Current Rating (Amps): 250mA; Height (Max): 0.33mm; Manufacturer: muRata; Manufacturer Part Number: LQP03TN12NJ02D; Package / Case: 0201; ROHS: Yes; SMT: Yes; Size / Dimension: 0.60mm x 0.30mm; Unit: PCS
R9 R10 = R0201: RES|Thick Film|0201|240Ω±5%|1/20W|±200ppm/°C; Height (Max): 0.26mm; Manufacturer: Yageo; Manufacturer Part Number: RC0201JR-07240RL; Package / Case: 0201; Power (Watts): 1/20W; ROHS: Yes; SMT: Yes; Size / Dimension: 0.60mm x 0.30mm; Tolerance: ±5%; Unit: PCS
U3 = PA_SKY77590_0
C27 C28 = C0201: CAP|MLCC|0201|3pF±0.25pF|25V|C0G; Height (Max): 0.33mm; Manufacturer: muRata; Manufacturer Part Number: GRM0335C1E3R0CA01D; Package / Case: 0201; Part Number: 351000000124; ROHS: Yes; SMT: Yes; Size / Dimension: 0.60mm x 0.30mm; Tolerance: ±0.25pF; Unit: PCS; Voltage - Rated: 25V
C30 C32 = C0201: CAP|MLCC|0201|0.1μF±10%|6.3V|X5R; Height (Max): 0.33mm; Manufacturer: muRata; Manufacturer Part Number: GRM033R60J104KE19D; Package / Case: 0201; Part Number: 351000000077; ROHS: Yes; SMT: Yes; Size / Dimension: 0.60mm x 0.30mm; Tolerance: ±10%; Unit: PCS; Voltage - Rated: 6.3V
L5 = L0201: IND|Thin Film|0201|22nH±5%|150mA|1.9Ω|Q12|2.2GHz; Current Rating (Amps): 150mA; Height (Max): 0.33mm; Manufacturer: muRata; Manufacturer Part Number: LQP03TN22NJ02D; Package / Case: 0201; ROHS: Yes; SMT: Yes; Size / Dimension: 0.60mm x 0.30mm; Unit: PCS
L6 = L0201: IND|Thin Film|0201|15nH±5%|250mA|700mΩ|Q12|2.6GHz; Current Rating (Amps): 250mA; Height (Max): 0.33mm; Manufacturer: muRata; Manufacturer Part Number: LQP03TN15NJ02D; Package / Case: 0201; ROHS: Yes; SMT: Yes; Size / Dimension: 0.60mm x 0.30mm; Unit: PCS
L7 = L0201: IND|Thin Film|0201|5.6nH±5%|350mA|400mΩ|Q14|4GHz; Current Rating (Amps): 350mA; Height (Max): 0.33mm; Manufacturer: muRata; Manufacturer Part Number: LQP03TN5N6J02D; Package / Case: 0201; ROHS: Yes; SMT: Yes; Size / Dimension: 0.60mm x 0.30mm; Unit: PCS
L8 = L0201: IND|Thin Film|0201|2.4nH±0.2nH|500mA|200mΩ|Q14|10GHz; Current Rating (Amps): 500mA; Height (Max): 0.33mm; Manufacturer: muRata; Manufacturer Part Number: LQP03TN2N4C02D; Package / Case: 0201; ROHS: Yes; SMT: Yes; Size / Dimension: 0.60mm x 0.30mm; Unit: PCS
L10 = L0201: IND|Thin Film|0201|27nH±5%|140mA|2.3Ω|Q12|2GHz; Current Rating (Amps): 140mA; Height (Max): 0.33mm; Manufacturer: muRata; Manufacturer Part Number: LQP03TN27NJ02D; Package / Case: 0201; ROHS: Yes; SMT: Yes; Size / Dimension: 0.60mm x 0.30mm; Unit: PCS
L11 = L0201: IND|Thin Film|0201|3.2nH±0.2nH|450mA|250mΩ|Q14|8GHz; Current Rating (Amps): 450mA; Height (Max): 0.33mm; Manufacturer: muRata; Manufacturer Part Number: LQP03TN3N2C02D; Package / Case: 0201; ROHS: Yes; SMT: Yes; Size / Dimension: 0.60mm x 0.30mm; Unit: PCS
U2 = MT2625
X2 = TSX_CT2520DB26000C0FZZA1_0: XTAL|2016|26MHz; FS: Y; Manufacturer: Kyocera; Manufacturer Part Number: CT2520DB26000C0FZZA1; Part_Number: X52-CT2520DB26000C; Property1: 26M; Unit: PCS; Vendor: KYOCERA; Vendor_PN: CT2520DB26000C0FZZA1

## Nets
AVDD33_VSIM_MT2625: C6.1 TP_1.2 U2.L6(AVDD33_VSIM)
AVDD33_VUSB_MT2625: C5.1 R3.2 TP12.1 U2.L8(AVDD33_VUSB)
GND_POWER: C1.1 C2.1 C4.2 C5.2 C6.2 C7.1 C8.1 C9.2 C10.2 C11.2 C12.2 C13.1 C14.2 C15.2 C16.2 C17.2 C18.2 C19.2 C20.2 C21.2 C22.2 C24.2 C25.2 C27.2 C28.2 C29.2 C30.2 C31.2 C32.2 C33.2 C34.2 C35.2 C36.2 C40.2 C41.2 C42.2 C43.1 C44.2 C45.2 C46.2 C47.2 C48.2 CON1.22(GND) CON1.23(GND) CON1.25(GND) CON1.26(GND) CON1.28(GND) CON1.29(GND) CON1.30(GND) L6.2 L8.2 L14.2 L15.2 R2.1 R4.1 TP5.1 U1.C2(GND) U2.A11(AVSS_RF_1) U2.B2(GND_7) U2.B4(GND_9) U2.B7(FSOURCE_P) U2.B10(LNA_OPIS) U2.C8(AVSS_RF_3) U2.C9(AVSS_RF_2) U2.D9(AVSS_RF_4) U2.D10(EXT_CLK_SEL) U2.E2(GND_8) U2.E5(GND_10) U2.E6(GND_5) U2.E7(GND_3) U2.F6(GND_1) U2.F7(GND_4) U2.F10(AVSS_DCXO_1) U2.F11(AVSS_DCXO_2) U2.G2(PMU_TESTMODE) U2.G5(GND_11) U2.G6(GND_2) U2.G7(GND_12) U2.H2(AVSS33_VRF) U2.H5(AVSS33_LDO) U2.J2(AVSS33_VPA) U2.J8(GND_6) U2.K2(AVSS33_VCORE) U2.L5(GND_VREF) U3.2(GND) U3.3(GND) U3.5(GND) U3.6(GND) U3.7(GND) U3.8(GND) U3.13(GND) U3.15(GND) U3.17(GND) U3.19(GND) U3.21(GND) U3.25(GND) X2.2(GND) X2.4(GND)
VBAT: C1.2 CON1.31(VCC) CON1.32(VCC) TP4.1 U1.A1(EN) U1.A2(VIN) U2.K4(AVDD45_VBATSNS)
ADC0_MT2625: CON1.38(ADC) U2.K8(GPIO30)
ANT_MT2625: CON1.27(ANT) L14.1 R7.1
AP_JTCK: TP2.1 U2.H7(GPIO34)
AP_JTMS: TP1.1 U2.H8(GPIO33)
AP_READY_MT2625: CON1.39(RESERVED) U2.F3(GPIO29)
GPIO0_MT2625: TP11.1 U2.A6(GPIO0)
I2C0_SCL_MT2625: CON1.36(I2C_SCL) U2.A4(GPIO6)
I2C0_SDA_MT2625: CON1.37(I2C_SDA) U2.A5(GPIO7)
LNA_LB_MT2625: L5.1 L6.1 U2.A10(LNA_LB)
LNA_MB2_MT2625: L7.1 L8.1 U2.C10(LNA_MB2)
LX_VCORE: L3.1 U2.L1(LX_VCORE)
LX_VPA: L4.1 U2.J1(LX_VPA)
LX_VRF: L2.1 U2.G1(LX_VRF)
MD_GPIO0_MT2625: CON1.34(GPIO) U2.A3(GPIO9)
MD_GPIO1_MT2625: CON1.35(GPIO) U2.A2(GPIO10)
MD_WAKEUP_MT2625: CON1.16(WAKEUP_OUT) U2.F2(GPIO27)
MIPI0_SCLK_MT2625: R10.2 U2.H10(MIPI_SCLK)
MIPI0_SDATA_MT2625: R9.2 U2.H11(MIPI_SDATA)
PMU_PWRKEY_MT2625: CON1.19(POWER_ON) R5.1 TP10.1
PMU_SYSRSTB_MT2625: CON1.17(RESET_B) R6.1 TP3.1
RTC_EINT_MT2625: CON1.18(WAKEUP_IN) U2.J6(RTC_EINT)
RX_LB: C21.1 C34.1 L5.2 L12.2
RX_MB2: C22.1 C36.1 L7.2 L13.2
SIM_DET_MT2625: CON1.11(USIM_DETECT) U2.J10(GPIO35)
SIM_SCLK_MT2625: CON1.13(USIM_CLK) U2.L11(SIM0_SCLK)
SIM_SIO_MT2625: CON1.14(USIM_DATA) U2.K10(SIM0_SIO)
SIM_SRST_MT2625: CON1.12(USIM_RESET) U2.K11(SIM0_SRST)
SPI_CS_MT2625: CON1.3(SPI_CS) U2.A1(GPIO12)
SPI_MISO_MT2625: CON1.4(SPI_MISO) U2.B1(GPIO14)
SPI_MOSI_MT2625: CON1.5(SPI_MOSI) U2.D5(GPIO13)
SPI_SCK_MT2625: CON1.6(SPI_CLK) U2.C3(GPIO15)
STATUS_MT2625: CON1.21(SYS_STATE) U2.G4(GPIO26)
TPS62088_3V3: C2.2 C3.1 C16.1 C17.1 C18.1 C19.1 C20.1 L1.2 R1.2 R8.2 TP_1.1 U2.H1(AVDD33_VRF) U2.K1(AVDD33_VPA) U2.K3(AVDD33_VPA_CTRL) U2.L2(AVDD33_VCORE) U2.L3(AVDD33_LDO)
TX_LB: C25.1 L9.2 U3.16(LB_TX)
TX_MB2: C28.1 L11.2 U3.14(MB_TX)
TXO_LB_MT2625: C23.1 U2.A9(TXO_LB)
TXO_MB2_MT2625: C26.1 U2.B8(TXO_MB2)
UART0_RXD_MT2625: CON1.2(UART2_RXD) TP7.1 U2.B5(GPIO2)
UART0_TXD_MT2625: CON1.1(UART2_TXD) TP6.1 U2.D6(GPIO5)
UART1_CTS_MT2625: CON1.7(UART1_CTS) U2.D4(GPIO18)
UART1_RTS_MT2625: CON1.8(UART1_RTS) U2.D1(GPIO23)
UART1_RXD_MT2625: CON1.10(UART1_RXD) TP9.1 U2.C4(GPIO16)
UART1_TXD_MT2625: CON1.9(UART1_TXD) TP8.1 U2.C2(GPIO17)
USB11_DM_MT2625: TP14.1 U2.K9(USB11_DM)
USB11_DP_MT2625: TP13.1 U2.L9(USB11_DP)
USB_EINT(GPIO36): R3.1 R4.2 U2.G8(GPIO36)
VCORE_MT2625: C8.2 L3.2 U2.E1(VDDK_2) U2.H9(VDDK_1) U2.J4(FB_VCORE)
VFEM_MT2625: C10.1 C43.2 U2.K6(VFEM) U3.9(VIO)
VIO18_MT2625: C4.1 C9.1 C29.1 C30.1 CON1.20(VDD) L10.1 U2.C1(DVDD_IO_0) U2.C5(DVDD_IO_2) U2.F1(DVDD18_MLDO) U2.J11(DVDD_IO_1) U2.L4(VIO18)
VPA_MT2625: C13.2 FB1.1 L4.2 U2.H4(FB_VPA)
VRF_MT2625: C7.2 C31.1 C32.1 L2.2 U2.D11(AVDD_RF) U2.H3(FB_VRF)
VSIM_MT2625: C12.1 CON1.15(USIM_VCC) U2.L10(VSIM)
VSRAM_RTC_MT2625: C11.1 U2.J5(VSRAM_RTC)
XIN_MT2625: C14.1 U2.K7(XIN) X1.1
XOUT_MT2625: C15.1 U2.L7(XOUT) X1.2
XTAL1_MT2625: U2.E11(XTAL1) X2.1(HOT)
XTAL2_MT2625: U2.E10(XTAL2) X2.3(HOT)
N27585593: L1.1 U1.B2(SW)
N27585738: C3.2 R1.1 R2.2 U1.C1(FB)
N27589160: R5.2 U2.K5(PMU_PWRKEY)
N27589192: R6.2 U2.J3(PMU_SYSRSTB)
N27593456: C42.1 C46.1 C47.1 C48.1 FB1.2 U3.18(VCC1) U3.20(VCC2)
N27593718: C39.1 L15.1 R7.2
N27593784: C39.2 U3.4(ANT)
N27593790: C44.1 R10.1 U3.10(SCLK)
N27593794: C45.1 R9.1 U3.11(SDATA)
N27593808: C40.1 C41.1 R8.1 U3.12(VBAT)
N27593970: C33.1 C37.2 L12.1
N27594005: C35.1 C38.2 L13.1
N27594054: C37.1 U3.22(TRX4)
N27594058: C38.1 U3.23(TRX3)
N27594777: C23.2 C24.1 L9.1
N27594947: L10.2 U2.E9(AVDD18_RF)
N27594957: C26.2 C27.1 L11.1

Not connected (* = marked no-connect by the designer): CON1 24(GNSS_ANT)* 33(RTC_Power)* 40(RESERVED)*; U1 B1(PG)*; U2 A7(RESETB_OUT)* A8(TXO_MB1)* B3(GPIO11)* B6(GPIO1)* B9(TXO_ULB)* B11(LNA_ULB)* C6(GPIO4)* C7(GPIO3)* C11(LNA_MB1)* D2(GPIO22)* D3(GPIO19)* D7(GPIO8)* D8(BPI0)* E3(GPIO25)* E4(GPIO20)* E8(BPI2)* F4(GPIO24)* F5(GPIO21)* F8(BPI1)* F9(BPI4)* G3(GPIO28)* G9(SRCLKENAI)* G10(BPI3)* G11(FREF)* H6(GPIO32)* J7(RTC_GPIO0)* J9(GPIO31)*; U3 1(TRX1)* 24(TRX2)*

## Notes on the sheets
sheet 1
- Project Name: TV_V1.0
- Version
- Date
- Description
- Note
- Author
- Sheets：
- 1.0
- 2020-2-18
- Initial Release
- James
- 01-Cover
- 1.1
- 2020-4-8
- Change U1 to TPS62088YFP, and update U1 related circuit
- James
- 02-Block Diagram
- 03-BATTERY
- 04-BB_MT2625_NBIOT_DBB
- 05-BB_MT2625_NBIOT_ABB
- 06-RF_MT2625_NBIOT_Transivier
- 07-RF_MT2625_NBIOT_FEM
- 08-DEBUG_IO
sheet 2
- FEM
  SKY6808
- 40Pin
  Connector
- MT2625
- DCDC
  VBAT>3.3V
  TPS62088YFP
- 32KHz
  XTAL
- 26MHz
  XTAL
sheet 3
- VBAT input (Li-ion battery or AC adapter, 3.4V-5V)
- 3.3V, 1A
- 3.4-5V
sheet 5
- RTC (32kHz)
- 6mils
- 4mils
- 12mils
- 20mils
- 4mils
- Note: 17-1
- Note 17-1:
- Following capacitor should be closer to MT2625
- C1704 closer to MT2625.L2
- C1705 closer to MT2625.H1
- C1707 closer to MT2625.K1
sheet 6
- CRYS_2016
sheet 8
- Test Point of SWD
- AP_JTMS(GPIO33)
- AP_JTCK(GPIO34)
- Test Point
- VBAT
- GND
- UART0_TXD(GPIO5)
- UART0_RXD(GPIO2)
- UART1_TXD(GPIO17)
- UART1_RXD(GPIO16)
- PMU_PWRKEY
- GPIO0 (trap pin for USB DL)
